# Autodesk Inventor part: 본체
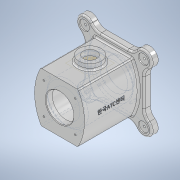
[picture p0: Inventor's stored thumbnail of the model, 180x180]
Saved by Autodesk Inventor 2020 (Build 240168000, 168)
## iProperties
Created: 2022-01
Part Number: 본체
Material: 알루미늄 6061
Document SubType Name: Modeling
Designer: USER
Density: 2.7 g/cm^3
Appearance: 알루미늄 - 연마
Mass: 1283.64 g
Surface Area: 918.697 cm^2
Volume: 475.421 cm^3
Author: USER
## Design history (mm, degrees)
sketch "스케치1"
  geometry: L1 (-54, -54)-(54, 54); L2 (-54, -25.008)-(-54, 25.008); L3 (-25.008, 54)-(25.008, 54); L4 (54, -54)-(51.619, -51.619); L5 (0, 0)-(-54, 54); L6 (54, 25.008)-(54, -25.008); L7 (25.008, -54)-(-25.008, -54); C1 r 2 at (-53.033, 53.033); C2 r 2 at (53.033, 53.033); C3 r 2 at (-53.033, -53.033); A1 r 75 centre (0, 0) between (-53.033, 53.033) and (53.033, 53.033); A2 r 15 centre (-53.033, 53.033) between (-41.022, 62.019) and (-62.019, 41.022); A3 r 15 centre (53.033, 53.033) between (62.019, 41.022) and (41.022, 62.019); A4 r 15 centre (53.033, -53.033) between (41.022, -62.019) and (62.019, -41.022); A5 r 15 centre (-53.033, -53.033) between (-62.019, -41.022) and (-41.022, -62.019); A6 r 20 centre (-74, 25.008) between (-54, 25.008) and (-62.019, 41.022); A7 r 20 centre (-25.008, 74) between (-41.022, 62.019) and (-25.008, 54); A8 r 20 centre (25.008, 74) between (25.008, 54) and (41.022, 62.019); A9 r 20 centre (74, 25.008) between (62.019, 41.022) and (54, 25.008); A10 r 20 centre (74, -25.008) between (54, -25.008) and (62.019, -41.022); A11 r 20 centre (25.008, -74) between (41.022, -62.019) and (25.008, -54); A12 r 20 centre (-25.008, -74) between (-25.008, -54) and (-41.022, -62.019); A13 r 20 centre (-74, -25.008) between (-62.019, -41.022) and (-54, -25.008); 9 further points
  constraints: 36 point on circle, 16 centre point, 16 tangent, 14 end point, 12 point on line, 11 equal radius, 5 coincident, 2 parallel, 1 horizontal, 1 midpoint, 1 perpendicular, 5 other
  dimensions: "d0" = 108 distance of L5.end L1.end; "d1" = 108 distance of L1.start L5.end; "d2" = 150 diameter of A1; "d3" = 30 diameter of A2; "d4" = 4 diameter of C1; "d5" = 20 radius of A6
extrude "돌출1" new body sketch "스케치1" distance "d6" = 12; taper "d7" = 0 deg
sketch "스케치2"
  geometry: L1 (33.054, -45)-(-33.054, -45); L2 (-45, -0.086)-(-45, 0.606); L3 (-33.724, 45)-(33.724, 45); L4 (45, 0.606)-(45, -0.086); L5 (45, -45)-(-45, 45); L6 (-45, -45)-(45, 45); L7 (0, 47.952)-(0, -51.745); L8 (-62.777, -0.086)-(68.35, -0.086); A1 r 93.031 centre (48.031, 0.606) between (-33.724, 45) and (-33.054, -45); A2 r 93.031 centre (-48.031, 0.606) between (33.054, -45) and (33.724, 45); 1 further point
  constraints: 16 end point, 6 point on circle, 3 symmetric about line, 2 centre point, 2 horizontal, 2 midpoint, 2 parallel, 2 point on line, 2 tangent, 1 perpendicular, 1 vertical, 1 other
  dimensions: "d8" = 90 distance of L5.end L6.end; "d9" = 90 distance of L6.end L5.start; "d10" = 93.03134 radius of A1; "d11" = 45.08642 distance between parallel lines of L8 L3; "d12" = 23.35019 distance from line of L8.end L4; "d13" = 0.69257 distance from line of A1.centre L8; "d14" = 48.03796 distance from line of L7.start L8; "d15" = 51.65905 distance from line of L7.end L8; "d16" = 107.77673 distance from line of L8.start L4
extrude "돌출2" join sketch "스케치2" distance "d17" = 98; taper "d18" = 0 deg
node "작업 평면1"
node "작업 평면3"
  node "작업 평면2"
sketch "스케치3"
  geometry: L1 (58.733, 12)-(8.716, 12) reference; C1 r 20 at (33.724, -43); 1 further point
  constraints: 1 centre point
  dimensions: "d21" = 40 diameter of C1; "d22" = 55 distance from line of L1 C1.centre
extrude "돌출3" join sketch "스케치3" distance "d23" = 30; taper "d24" = 0 deg
sketch "스케치4"
  geometry: C1 r 25 at (0, 0); 1 further point
  constraints: 1 centre point, 1 coincident
  dimensions: "d25" = 50 diameter of C1
extrude "돌출4" cut sketch "스케치4" extent not by distance; stored distance "d26" = 0; taper "d27" = 0 deg
node "작업 평면4"
sketch "스케치5"
  geometry: C1 r 37 at (0, 0); 1 further point
  constraints: 1 centre point, 1 coincident
  dimensions: "d29" = 74 diameter of C1
extrude "돌출5" cut sketch "스케치5" distance "d30" = 86; taper "d31" = 0 deg
sketch "스케치6"
  geometry: 1 further point
fillet "모깎기1" dims "d32" = 3
chamfer "모따기1" distance "d33" = 1; stored, may be unused: second distance "d34" = 2, angle "d35" = 45 deg
fillet "모깎기2" dims "d36" = 3
sketch "스케치7" dims "d37" = 80
  geometry: L1 (0, -59.816)-(0, 86.365) reference; L2 (-67.972, 0)-(59.976, 0) reference; L3 (0, 0)-(-58.946, 58.946); 2 further points
  constraints: 6 end point, 2 horizontal, 2 vertical, 1 coincident, 1 point on line, 3 other
  dimensions: "d38" = 45 deg angle of L3 L1
hole "구멍1" sketch "스케치7" at (-28.284, 28.284) diameter "d39" = 3.242; stored, may be unused: countersink angle "d43" = 90 deg, drill point angle "d45" = 118 deg; dims "d40" = 9, "d41" = 4, "d42" = 2, "d44" = 11
sketch "스케치8"
  geometry: C1 r 2 at (-53.033, 53.033) reference; C2 r 9 at (-53.033, 53.033); C3 r 2 at (53.033, 53.033) reference; C4 r 9 at (53.033, 53.033); 1 further point
  constraints: 2 centre point, 2 coincident, 1 equal radius
  dimensions: "d49" = 18 diameter of C2
extrude "돌출6" cut sketch "스케치8" distance "d50" = 2; taper "d51" = 0 deg
sketch "스케치9"
  geometry: C1 r 20 at (0, 0) reference; C2 r 12 at (0, 0); 1 further point
  constraints: 1 centre point, 1 coincident
  dimensions: "d52" = 24 diameter of C2
extrude "돌출7" cut sketch "스케치9" distance "d53" = 24; taper "d54" = 0 deg
node "작업 평면5"
sketch "스케치10"
  geometry: C1 r 12 at (31.92, -40) reference; C2 r 15 at (31.92, -40); 1 further point
  constraints: 1 centre point, 1 coincident
  dimensions: "d56" = 30 diameter of C2
extrude "돌출8" cut sketch "스케치10" distance "d57" = 24; taper "d58" = 0 deg
sketch "스케치11"
  geometry: 1 further point
fillet "모깎기3" dims "d59" = 1
sketch "스케치12"
  geometry: L1 (0, 0)-(0, 93.648) reference; L2 (0, 0)-(90.053, 0) reference; L3 (0, 0)-(82.995, 82.995); C1 r 40 at (0, 0); C2 r 25 at (0, 0) reference; C3 r 34 at (0, 0) reference; C4 r 1.621 at (28.284, 28.284) reference; 2 further points
  constraints: 6 end point, 2 coincident, 2 horizontal, 2 vertical, 1 centre point
  dimensions: "d60" = 80 diameter of C1; "d61" = 45 deg angle of L2 L3
hole "구멍2" sketch "스케치12" at (28.284, 28.284) diameter "d62" = 3.242; stored, may be unused: countersink angle "d66" = 90 deg, drill point angle "d68" = 118 deg; dims "d63" = 9, "d64" = 4, "d65" = 2, "d67" = 11
node "작업 평면7"
  node "작업 평면6"
sketch "스케치13"
  geometry: 2 further points
  constraints: 1 other
feature "엠보싱1" sketch "스케치13" dims "d73" = 1, "d74" = 0
node "솔리드1"
pattern_circular "원형 패턴1" dims angle "d47" = 360 deg
mirror "미러1"
pattern_circular "원형 패턴2" dims angle "d70" = 360 deg
feature "A9D066F2-1C7D-4E18-AEED-F7BC21143FA4" dims "d39" = 3.242, "d40" = 9, "d41" = 4, "d42" = 2, "d43" = 90 deg, "d44" = 11, "d45" = 118 deg
other parameters: "d19" = 0, "d20" = 55, "d28" = -12, "d55" = -13, "d72" = 49.5
